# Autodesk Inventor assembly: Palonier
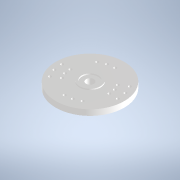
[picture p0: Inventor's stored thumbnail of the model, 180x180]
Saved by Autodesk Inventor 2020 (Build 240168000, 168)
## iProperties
Created: 2012-04
Part Number: Palonier
Document SubType Name: Assembly
Designer: bruno
Author: bruno
Sending System: SolidWorks 2010
Last Author: FBruyere
Last Saved: 2012-04-07
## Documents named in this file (3)
- C:\Users\bruno\Documents\1-Cours-2023-24\Maquettes-Inventor\Pince-robot-Dobot\HS422\Palonier.iam
- C:\Users\bruno\Documents\1-Cours-2023-24\Maquettes-Inventor\Pince-robot-Dobot\HS422\axe_HS422.ipt
- C:\Users\bruno\Documents\1-Cours-2023-24\Maquettes-Inventor\Pince-robot-Dobot\HS422\palonnier_HS422.ipt
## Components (2 placed, 2 different names)
1. axe_HS422:1
2. palonnier_HS422:1
